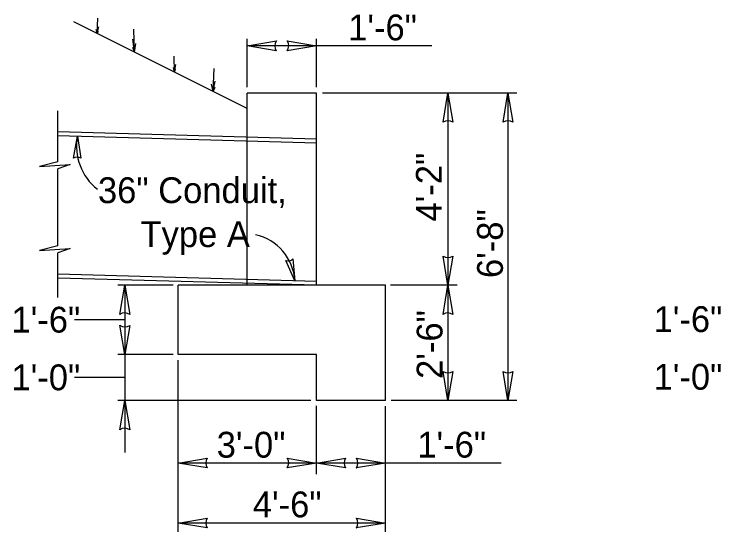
# Model space of a CAD drawing. Extents: x -30 to 76, y -31 to 50.
# Drawn here: x 21.059 to 24.892, y -21.543 to -18.737 of the extents above; entities that cross this region are included whole.
import ezdxf

# ---------------------------------------------------------------- set-up
doc = ezdxf.new("R2010")
doc.units = 0
for name, color, linetype in [('Default', 7, 'Continuous'), ('DR_P_Culvert', 7, 'Continuous'), ('DR_P_Headwall', 7, 'Continuous'), ('SH_Data', 7, 'Continuous'), ('XS_P_Finished_Grade', 7, 'Continuous'), ('XS_P_Headwall', 7, 'Continuous')]:
    doc.layers.add(name, color=color, linetype=linetype)

msp = doc.modelspace()

# ---------------------------------------------------------------- linework, layer by layer
at = {"layer": 'Default'}
for p, q in [((22.3232, -18.9091), (22.4815, -18.8827)), ((22.4815, -18.8827), (22.4814, -18.8827)), ((22.5404, -18.8827), (22.5404, -18.8827)), ((22.5404, -18.8827), (22.6982, -18.9091)), ((22.4809, -18.9354), (22.3232, -18.9091)), ((22.6982, -18.9091), (22.5399, -18.9354)), ((22.4809, -18.9354), (22.4809, -18.9354)), ((22.5399, -18.9354), (22.54, -18.9354)), ((23.3852, -19.3229), (23.4116, -19.1652)), ((23.4116, -19.1652), (23.4379, -19.3235)), ((23.7107, -19.3229), (23.737, -19.1652)), ((23.737, -19.1652), (23.7634, -19.3235)), ((23.3852, -19.3229), (23.3852, -19.3229)), ((23.4379, -19.3235), (23.4379, -19.3234)), ((23.7107, -19.3229), (23.7107, -19.3229)), ((23.7634, -19.3235), (23.7634, -19.3234)), ((21.3812, -19.5177), (21.4019, -19.3995)), ((21.4019, -19.3995), (21.4207, -19.5184)), ((21.3812, -19.5177), (21.3812, -19.5177)), ((21.4207, -19.5184), (21.4207, -19.5183)), ((22.5813, -20.1828), (22.5327, -20.0727)), ((22.5327, -20.0727), (22.5327, -20.0727)), ((22.571, -20.0632), (22.571, -20.0632)), ((22.571, -20.0632), (22.5813, -20.1828)), ((23.4116, -20.2068), (23.3852, -20.0486)), ((23.3852, -20.0486), (23.3852, -20.0487)), ((23.4379, -20.0491), (23.4116, -20.2068)), ((23.4379, -20.0491), (23.4379, -20.0491)), ((21.6332, -20.3646), (21.6595, -20.2068)), ((21.6595, -20.2068), (21.6859, -20.3651)), ((23.3852, -20.3646), (23.4116, -20.2068)), ((23.4116, -20.2068), (23.4379, -20.3651)), ((21.6332, -20.3646), (21.6332, -20.3646)), ((21.6859, -20.3651), (21.6859, -20.365)), ((23.3852, -20.3646), (23.3852, -20.3646)), ((23.4379, -20.3651), (23.4379, -20.365)), ((21.6595, -20.5818), (21.6332, -20.4236)), ((21.6332, -20.4236), (21.6332, -20.4237)), ((21.6859, -20.4241), (21.6595, -20.5818)), ((21.6859, -20.4241), (21.6859, -20.4241)), ((23.4116, -20.8318), (23.3852, -20.6736)), ((23.3852, -20.6736), (23.3852, -20.6737)), ((23.4379, -20.6741), (23.4116, -20.8318)), ((23.4379, -20.6741), (23.4379, -20.6741)), ((23.737, -20.8318), (23.7107, -20.6736)), ((23.7107, -20.6736), (23.7107, -20.6737)), ((23.7634, -20.6741), (23.737, -20.8318)), ((23.7634, -20.6741), (23.7634, -20.6741)), ((21.6332, -20.9896), (21.6595, -20.8318)), ((21.6595, -20.8318), (21.6859, -20.9901)), ((21.6332, -20.9896), (21.6332, -20.9896)), ((21.6859, -20.9901), (21.6859, -20.99)), ((21.9482, -21.1702), (22.1065, -21.1439)), ((22.1065, -21.1439), (22.1064, -21.1439)), ((22.5404, -21.1439), (22.5404, -21.1439)), ((22.5404, -21.1439), (22.6982, -21.1702)), ((22.6982, -21.1702), (22.8565, -21.1439)), ((22.8565, -21.1439), (22.8564, -21.1439)), ((22.9154, -21.1439), (22.9154, -21.1439)), ((22.9154, -21.1439), (23.0732, -21.1702)), ((22.1059, -21.1966), (21.9482, -21.1702)), ((22.6982, -21.1702), (22.5399, -21.1966)), ((22.8559, -21.1966), (22.6982, -21.1702)), ((23.0732, -21.1702), (22.9149, -21.1966)), ((22.1059, -21.1966), (22.1059, -21.1966)), ((22.5399, -21.1966), (22.54, -21.1966)), ((22.8559, -21.1966), (22.8559, -21.1966)), ((22.9149, -21.1966), (22.915, -21.1966)), ((21.9482, -21.4957), (22.1065, -21.4693)), ((22.1059, -21.522), (21.9482, -21.4957)), ((22.1065, -21.4693), (22.1064, -21.4693)), ((23.0732, -21.4957), (22.9149, -21.522)), ((22.9154, -21.4693), (22.9154, -21.4693)), ((22.9154, -21.4693), (23.0732, -21.4957)), ((22.1059, -21.522), (22.1059, -21.522)), ((22.9149, -21.522), (22.915, -21.522))]:
    msp.add_line(p, q, dxfattribs=at)
for centre, radius, start, end in [((22.5213, -18.9094), 0.048, 146.178, 212.8588), ((22.5001, -18.9087), 0.048, 326.178, 32.8588), ((23.4112, -19.3633), 0.048, 56.178, 122.8588), ((23.7366, -19.3633), 0.048, 56.178, 122.8588), ((21.4004, -19.5481), 0.036, 55.7008, 122.3816), ((22.5447, -20.0388), 0.036, 250.5691, 317.2499), ((23.412, -20.0088), 0.048, 236.178, 302.8588), ((21.6591, -20.4049), 0.048, 56.178, 122.8588), ((23.4112, -20.4049), 0.048, 56.178, 122.8588), ((21.6599, -20.3838), 0.048, 236.178, 302.8588), ((23.412, -20.6338), 0.048, 236.178, 302.8588), ((23.7374, -20.6338), 0.048, 236.178, 302.8588), ((21.6591, -21.0299), 0.048, 56.178, 122.8588), ((22.1463, -21.1706), 0.048, 146.178, 212.8588), ((22.5001, -21.1699), 0.048, 326.178, 32.8588), ((22.8963, -21.1706), 0.048, 146.178, 212.8588), ((22.8751, -21.1699), 0.048, 326.178, 32.8588), ((22.1463, -21.4961), 0.048, 146.178, 212.8588), ((22.8751, -21.4953), 0.048, 326.178, 32.8588)]:
    msp.add_arc(centre, radius, start, end, dxfattribs=at)
at = {"layer": 'DR_P_Culvert'}
for p, q in [((22.6982, -19.4149), (21.2969, -19.3757)), ((22.6982, -19.4357), (21.2969, -19.3966)), ((22.6982, -20.2069), (22.6982, -19.4149)), ((22.6982, -20.186), (21.2969, -20.1469)), ((22.6982, -20.2069), (21.2969, -20.1677))]:
    msp.add_line(p, q, dxfattribs=at)
at = {"layer": 'DR_P_Headwall'}
for p, q in [((22.6982, -19.1652), (22.3232, -19.1652)), ((22.3232, -19.4047), (22.3232, -19.1652)), ((22.6982, -19.4149), (22.6982, -19.1652)), ((22.3232, -20.1964), (22.3232, -19.4047)), ((22.3232, -20.2068), (22.3232, -20.1964)), ((21.9482, -20.5818), (21.9482, -20.2068)), ((22.3232, -20.2068), (21.9482, -20.2068)), ((22.6982, -20.2068), (22.3232, -20.2068)), ((23.0732, -20.2068), (22.6982, -20.2068)), ((23.0732, -20.8318), (23.0732, -20.2068)), ((22.6982, -20.5818), (21.9482, -20.5818)), ((22.6982, -20.8318), (22.6982, -20.5818)), ((23.0732, -20.8318), (22.6982, -20.8318))]:
    msp.add_line(p, q, dxfattribs=at)
at = {"layer": 'SH_Data'}
for p, q in [((22.3232, -19.1334), (22.3232, -18.8706)), ((22.6982, -19.1334), (22.6982, -18.8706)), ((22.6982, -18.9091), (22.3232, -18.9091)), ((23.3246, -18.9091), (22.6982, -18.9091)), ((23.7844, -19.1652), (22.7319, -19.1652)), ((23.4116, -19.1652), (23.4116, -20.2068)), ((23.737, -19.1652), (23.737, -20.8318)), ((21.9217, -20.2068), (21.6219, -20.2068)), ((21.6595, -20.2068), (21.6595, -20.5818)), ((23.4615, -20.2068), (23.1002, -20.2068)), ((23.4116, -20.2068), (23.4116, -20.8318)), ((21.6595, -20.3943), (21.3857, -20.3943)), ((21.9217, -20.5818), (21.6219, -20.5818)), ((21.6595, -20.5818), (21.6595, -20.8318)), ((21.9482, -21.5431), (21.9482, -20.6127)), ((21.6595, -20.7068), (21.3857, -20.7068)), ((22.6675, -20.8318), (21.6219, -20.8318)), ((21.6595, -20.8318), (21.6595, -21.1137)), ((23.7844, -20.8318), (23.1039, -20.8318)), ((22.6982, -21.2309), (22.6982, -20.8604)), ((23.0732, -21.5431), (23.0732, -20.8614)), ((22.6982, -21.1702), (21.9482, -21.1702)), ((23.0732, -21.1702), (22.6982, -21.1702)), ((23.6996, -21.1702), (23.0732, -21.1702)), ((23.0732, -21.4957), (21.9482, -21.4957))]:
    msp.add_line(p, q, dxfattribs=at)
for centre, radius, start, end in [((21.694, -19.4526), 0.2969, 169.7058, 231.8386), ((22.3121, -20.1975), 0.2696, 3.1279, 78.0841)]:
    msp.add_arc(centre, radius, start, end, dxfattribs=at)
at = {"layer": 'XS_P_Finished_Grade'}
for p, q in [((22.3232, -19.2485), (21.3823, -18.7781)), ((21.5095, -18.8417), (21.5135, -18.7585)), ((21.5095, -18.8417), (21.5189, -18.8059)), ((21.5095, -18.8417), (21.5037, -18.8202)), ((21.5095, -18.8417), (21.5165, -18.8291)), ((21.7112, -18.9425), (21.7084, -18.8184)), ((21.7112, -18.9425), (21.703, -18.8723)), ((21.7112, -18.9425), (21.703, -18.918)), ((21.7112, -18.9425), (21.7191, -18.8965)), ((21.929, -19.0514), (21.9277, -18.9654)), ((21.929, -19.0514), (21.9232, -19.0272)), ((21.929, -19.0514), (21.9357, -19.0101)), ((21.929, -19.0514), (21.9343, -19.036)), ((22.1379, -19.1559), (22.1439, -19.0311)), ((22.1379, -19.1559), (22.129, -19.1165)), ((22.1379, -19.1559), (22.1495, -19.1013)), ((22.1379, -19.1559), (22.1486, -19.1335))]:
    msp.add_line(p, q, dxfattribs=at)
at = {"layer": 'XS_P_Headwall'}
for p, q in [((21.2969, -19.537), (21.2969, -19.2607)), ((21.2969, -19.537), (21.1966, -19.5627)), ((21.1966, -19.5627), (21.3636, -19.5526)), ((21.3636, -19.5526), (21.2969, -19.5756)), ((21.2969, -19.9927), (21.2969, -19.5756)), ((21.2969, -19.9927), (21.1966, -20.0183)), ((21.1966, -20.0183), (21.3636, -20.0083)), ((21.3636, -20.0083), (21.2969, -20.0313)), ((21.2969, -20.2731), (21.2969, -20.0313))]:
    msp.add_line(p, q, dxfattribs=at)

# ---------------------------------------------------------------- texts
at = {"layer": 'SH_Data'}
for s, p in [('1\'-6"', (22.8707, -18.8794)), ('36" Conduit,', (21.5137, -19.7616)), ('Type A', (21.7444, -19.9996)), ('1\'-6"', (21.0449, -20.4632)), ('1\'-6"', (24.5269, -20.4602)), ('1\'-0"', (21.0449, -20.7757)), ('1\'-0"', (24.5269, -20.7727)), ('3\'-0"', (22.1577, -21.1409)), ('1\'-6"', (23.2457, -21.1406)), ('4\'-6"', (22.3536, -21.4643))]:
    msp.add_text(s, height=0.14, dxfattribs=at).set_placement(p)
for s, p in [('4\'-2"', (23.3782, -19.8612)), ('6\'-8"', (23.7097, -20.1675)), ('2\'-6"', (23.3822, -20.7142))]:
    msp.add_text(s, height=0.14, rotation=90, dxfattribs=at).set_placement(p)

doc.saveas('drawing.dxf')
